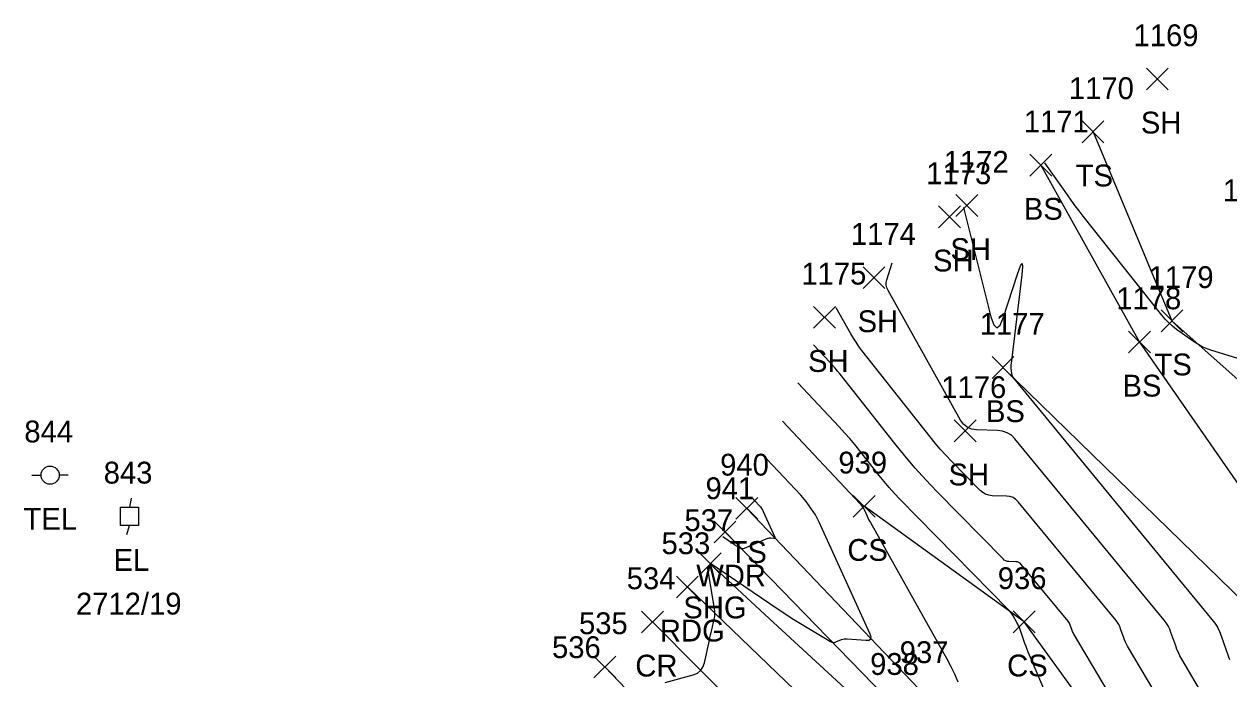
# Model space of a CAD drawing. Extents: x 1592612 to 1596497, y 111838 to 113741.
# Drawn here: x 1592611.9 to 1592722.3, y 113631.2 to 113691.2 of the extents above; entities that cross this region are included whole.
import ezdxf

# ---------------------------------------------------------------- set-up
doc = ezdxf.new("R2010")
doc.units = 0
for name, color, linetype in [('L_A', 7, 'Continuous'), ('L_I', 7, 'Continuous'), ('L_TIC', 7, 'Continuous'), ('LAWA', 7, 'Continuous'), ('LELB', 7, 'Continuous'), ('LSOGCMA', 7, 'Continuous'), ('LSOGCMI', 7, 'Continuous'), ('P_A', 7, 'Continuous'), ('P_I', 7, 'Continuous'), ('P_TIC', 7, 'Continuous'), ('PEU', 7, 'Continuous'), ('PRC', 7, 'Continuous'), ('PSU', 7, 'Continuous'), ('U_A', 7, 'Continuous'), ('U_C', 7, 'Continuous'), ('U_I', 7, 'Continuous'), ('UEPT', 7, 'Continuous'), ('UP', 7, 'Continuous')]:
    doc.layers.add(name, color=color, linetype=linetype)

msp = doc.modelspace()

# ---------------------------------------------------------------- linework, layer by layer
at = {"layer": 'L_TIC'}
for points in [[(1592714.73, 113685.21), (1592716.73, 113687.21)], [(1592716.73, 113685.21), (1592714.73, 113687.21)], [(1592708.84, 113680.36), (1592710.84, 113682.36)], [(1592710.84, 113680.36), (1592708.84, 113682.36)], [(1592704.06, 113677.31), (1592706.06, 113679.31)], [(1592706.06, 113677.31), (1592704.06, 113679.31)], [(1592697.28, 113673.62), (1592699.28, 113675.62)], [(1592699.28, 113673.62), (1592697.28, 113675.62)], [(1592695.69, 113672.57), (1592697.69, 113674.57)], [(1592697.69, 113672.57), (1592695.69, 113674.57)], [(1592688.78, 113667.01), (1592690.78, 113669.01)], [(1592690.78, 113667.01), (1592688.78, 113669.01)], [(1592684.24, 113663.37), (1592686.24, 113665.37)], [(1592686.24, 113663.37), (1592684.24, 113665.37)], [(1592716.07, 113663.05), (1592718.07, 113665.05)], [(1592718.07, 113663.05), (1592716.07, 113665.05)], [(1592713.1, 113661.11), (1592715.1, 113663.11)], [(1592715.1, 113661.11), (1592713.1, 113663.11)], [(1592700.59, 113658.77), (1592702.59, 113660.77)], [(1592702.59, 113658.77), (1592700.59, 113660.77)], [(1592697.12, 113652.97), (1592699.12, 113654.97)], [(1592699.12, 113652.97), (1592697.12, 113654.97)], [(1592677.13, 113645.87), (1592679.13, 113647.87)], [(1592679.13, 113645.87), (1592677.13, 113647.87)], [(1592687.88, 113646.06), (1592689.88, 113648.06)], [(1592689.88, 113646.06), (1592687.88, 113648.06)], [(1592675.13, 113643.71), (1592677.13, 113645.71)], [(1592677.13, 113643.71), (1592675.13, 113645.71)], [(1592702.53, 113635.47), (1592704.53, 113637.47)], [(1592704.53, 113635.47), (1592702.53, 113637.47)]]:
    msp.add_lwpolyline(points, dxfattribs=at)
at = {"layer": 'LAWA'}
msp.add_lwpolyline([(1592820.85, 113504.77), (1592798.01, 113529.8), (1592767.97, 113554.76), (1592744.7, 113575.87), (1592731.75, 113590.19), (1592719.52, 113602.85), (1592702.93, 113618.44), (1592691.78, 113628.61), (1592676.13, 113644.71)], dxfattribs=at)
at = {"layer": 'LELB'}
for points in [[(1592709.84, 113681.36), (1592717.07, 113664.05), (1592736.4, 113646.87), (1592747.92, 113636.87), (1592767.3, 113626.29), (1592768.75, 113634.43)], [(1592705.06, 113678.31), (1592714.1, 113662.11), (1592730.21, 113638.89), (1592746.13, 113634.3), (1592770.55, 113620.75), (1592772.37, 113634.85)], [(1592701.59, 113659.77), (1592726.1, 113635.89), (1592737.45, 113625.12), (1592757.27, 113620.55), (1592765.53, 113604.49), (1592785.22, 113593.36), (1592785.14, 113579.95), (1592783.1, 113567.94), (1592785.83, 113560.01), (1592797.4, 113544.62), (1592809.21, 113533.64), (1592811.43, 113524.52), (1592820.84, 113522.69), (1592826.43, 113512.91)], [(1592694.49, 113629.69), (1592678.13, 113646.87)], [(1592719.55, 113614.32), (1592703.53, 113636.47), (1592688.88, 113647.06)]]:
    msp.add_lwpolyline(points, dxfattribs=at)
at = {"layer": 'LSOGCMA'}
for points in [[(1592721.65, 113626.83), (1592717.96, 113633.06), (1592717.8, 113633.35), (1592717.66, 113633.65), (1592717.53, 113633.95), (1592717.41, 113634.26), (1592716.98, 113635.51), (1592716.86, 113635.81), (1592716.71, 113636.11), (1592716.54, 113636.38), (1592716.34, 113636.64), (1592702.69, 113653.24), (1592702.36, 113653.56), (1592701.98, 113653.8), (1592701.56, 113653.95), (1592701.1, 113654.01), (1592699.16, 113654.06), (1592698.7, 113654.13), (1592698.31, 113654.3), (1592697.98, 113654.57), (1592697.71, 113654.94), (1592691.06, 113666.83), (1592690.95, 113667.07), (1592690.9, 113667.31), (1592690.9, 113667.56), (1592690.96, 113667.81), (1592691.45, 113669.35)], [(1592674.81, 113641.86), (1592681, 113637.63), (1592681.32, 113637.41), (1592681.64, 113637.2), (1592681.97, 113637), (1592682.29, 113636.79), (1592685.8, 113634.67), (1592685.92, 113634.61), (1592686.04, 113634.59), (1592686.16, 113634.59), (1592686.28, 113634.63), (1592686.79, 113634.85), (1592686.91, 113634.89), (1592687.04, 113634.92), (1592687.17, 113634.93), (1592687.31, 113634.93), (1592689.03, 113634.78), (1592689.31, 113634.8), (1592689.46, 113634.89), (1592689.5, 113635.07), (1592689.42, 113635.33), (1592684.74, 113645.6), (1592684.4, 113646.27), (1592684, 113646.9), (1592683.56, 113647.51), (1592683.07, 113648.07), (1592679.97, 113651.38)], [(1592670.63, 113630.92), (1592673.21, 113631.63), (1592673.59, 113631.78), (1592673.88, 113632.01), (1592674.1, 113632.32), (1592674.24, 113632.71), (1592674.7, 113634.78), (1592674.75, 113635.02), (1592674.81, 113635.27), (1592674.86, 113635.51), (1592674.92, 113635.75), (1592675.14, 113636.71), (1592675.18, 113636.95), (1592675.2, 113637.2), (1592675.2, 113637.44), (1592675.17, 113637.68), (1592674.51, 113641.52)]]:
    msp.add_lwpolyline(points, dxfattribs=at)
at = {"layer": 'LSOGCMI'}
for points in [[(1592736.06, 113656.62), (1592720.72, 113661.33), (1592720.28, 113661.49), (1592719.85, 113661.68), (1592719.44, 113661.9), (1592719.04, 113662.16), (1592717.5, 113663.27), (1592717.12, 113663.56), (1592716.77, 113663.88), (1592716.44, 113664.21), (1592716.13, 113664.57), (1592708.94, 113673.65), (1592708.57, 113674.12), (1592708.2, 113674.6), (1592707.84, 113675.09), (1592707.49, 113675.58), (1592705.41, 113678.53)], [(1592697.98, 113674.42), (1592700.49, 113664.43), (1592700.75, 113663.67), (1592701.03, 113663.42), (1592701.33, 113663.65), (1592701.64, 113664.39), (1592702.92, 113668.34), (1592703.19, 113669.08), (1592703.34, 113669.31), (1592703.38, 113669.03), (1592703.31, 113668.26), (1592702.33, 113660.14), (1592702.32, 113660.02), (1592702.31, 113659.91), (1592702.31, 113659.79), (1592702.32, 113659.68), (1592702.37, 113659.22), (1592702.39, 113659.1), (1592702.43, 113659), (1592702.48, 113658.9), (1592702.54, 113658.81), (1592720.73, 113636.7), (1592721, 113636.35), (1592721.23, 113635.98), (1592721.43, 113635.59), (1592721.59, 113635.18), (1592722.22, 113633.35), (1592722.35, 113633.01)], [(1592720.71, 113621.24), (1592713.01, 113634.23), (1592712.91, 113634.42), (1592712.81, 113634.62), (1592712.73, 113634.81), (1592712.65, 113635.02), (1592712.36, 113635.84), (1592712.29, 113636.04), (1592712.19, 113636.23), (1592712.08, 113636.41), (1592711.95, 113636.59), (1592702.99, 113647.47), (1592702.76, 113647.69), (1592702.51, 113647.86), (1592702.23, 113647.96), (1592701.92, 113648), (1592700.6, 113648.03), (1592700.29, 113648.07), (1592700, 113648.16), (1592699.73, 113648.31), (1592699.49, 113648.52), (1592696.86, 113651.2), (1592696.35, 113651.73), (1592695.85, 113652.28), (1592695.38, 113652.84), (1592694.91, 113653.41), (1592688.67, 113661.34), (1592688.39, 113661.7), (1592688.13, 113662.08), (1592687.89, 113662.46), (1592687.66, 113662.85), (1592686.31, 113665.23)], [(1592719.77, 113615.64), (1592708.06, 113635.4), (1592708.01, 113635.49), (1592707.97, 113635.59), (1592707.92, 113635.68), (1592707.89, 113635.78), (1592707.75, 113636.17), (1592707.71, 113636.27), (1592707.67, 113636.36), (1592707.61, 113636.44), (1592707.55, 113636.53), (1592703.27, 113641.73), (1592703.16, 113641.84), (1592703.04, 113641.91), (1592702.91, 113641.96), (1592702.76, 113641.98), (1592702.13, 113642), (1592701.98, 113642.01), (1592701.84, 113642.06), (1592701.71, 113642.13), (1592701.6, 113642.23), (1592695.54, 113648.4), (1592694.53, 113649.47), (1592693.54, 113650.55), (1592692.59, 113651.67), (1592691.67, 113652.81), (1592686.67, 113659.15), (1592686.44, 113659.44), (1592686.21, 113659.72), (1592685.97, 113659.99), (1592685.72, 113660.26), (1592684.22, 113661.86)], [(1592709.06, 113621.56), (1592704.01, 113633.41), (1592703.9, 113633.68), (1592703.8, 113633.94), (1592703.7, 113634.21), (1592703.6, 113634.48), (1592703.15, 113635.77), (1592703.09, 113635.94), (1592703.02, 113636.1), (1592702.95, 113636.25), (1592702.87, 113636.41), (1592702.52, 113637.02), (1592702.43, 113637.17), (1592702.33, 113637.31), (1592702.22, 113637.45), (1592702.11, 113637.57), (1592692.15, 113647.72), (1592691.66, 113648.24), (1592691.17, 113648.77), (1592690.71, 113649.32), (1592690.25, 113649.88), (1592688.47, 113652.15), (1592688.02, 113652.71), (1592687.55, 113653.26), (1592687.08, 113653.8), (1592686.59, 113654.33), (1592682.8, 113658.36)], [(1592681.38, 113654.87), (1592688.5, 113647.29), (1592688.61, 113647.17), (1592688.7, 113647.04), (1592688.79, 113646.9), (1592688.86, 113646.75), (1592689.14, 113646.15), (1592689.21, 113646), (1592689.28, 113645.85), (1592689.36, 113645.71), (1592689.44, 113645.56), (1592696.44, 113633.07), (1592696.81, 113632.39), (1592697.14, 113631.7), (1592697.44, 113630.99)], [(1592678.55, 113647.89), (1592679.25, 113647.14), (1592679.37, 113647.01), (1592679.47, 113646.87), (1592679.55, 113646.73), (1592679.63, 113646.58), (1592680.7, 113644.24), (1592680.72, 113644.18), (1592680.71, 113644.14), (1592680.67, 113644.12), (1592680.61, 113644.12), (1592680.31, 113644.14), (1592680.23, 113644.15), (1592680.16, 113644.14), (1592680.09, 113644.12), (1592680.02, 113644.1), (1592677.88, 113643.18), (1592677.79, 113643.15), (1592677.7, 113643.15), (1592677.61, 113643.17), (1592677.52, 113643.21), (1592677.1, 113643.46), (1592677.05, 113643.49), (1592677, 113643.53), (1592676.95, 113643.56), (1592676.9, 113643.59), (1592675.92, 113644.26)]]:
    msp.add_lwpolyline(points, dxfattribs=at)
at = {"layer": 'P_TIC'}
for points in [[(1592673.78, 113640.79), (1592675.78, 113642.79)], [(1592675.78, 113640.79), (1592673.78, 113642.79)], [(1592671.68, 113638.67), (1592673.68, 113640.67)], [(1592673.68, 113638.67), (1592671.68, 113640.67)], [(1592668.48, 113635.46), (1592670.48, 113637.46)], [(1592670.48, 113635.46), (1592668.48, 113637.46)], [(1592664.11, 113631.34), (1592666.11, 113633.34)], [(1592666.11, 113631.34), (1592664.11, 113633.34)]]:
    msp.add_lwpolyline(points, dxfattribs=at)
at = {"layer": 'PEU'}
for points in [[(1592852.27, 113463.85), (1592836.28, 113474.06), (1592819.97, 113487.62), (1592800.66, 113505.5), (1592780.78, 113527.09), (1592759.62, 113549.57), (1592738.37, 113572.94), (1592716.19, 113596.28), (1592693.96, 113619.19), (1592672.68, 113639.67)], [(1592744.66, 113547.12), (1592739.3, 113552.77), (1592733.95, 113558.42), (1592728.59, 113564.06), (1592723.23, 113570.05), (1592717.86, 113576.03), (1592712.5, 113582.01), (1592707.13, 113587.99), (1592701.82, 113593.63), (1592696.51, 113599.28), (1592691.19, 113604.92), (1592685.88, 113610.56), (1592680.69, 113616.01), (1592675.49, 113621.45), (1592670.3, 113626.9), (1592665.11, 113632.34)]]:
    msp.add_lwpolyline(points, dxfattribs=at)
at = {"layer": 'PRC'}
msp.add_lwpolyline([(1592851.01, 113460.15), (1592833.1, 113469.52), (1592815.86, 113483.2), (1592796.57, 113501.27), (1592777.29, 113523.93), (1592756.26, 113546.33), (1592734.61, 113569.35), (1592712.84, 113593.06), (1592690.49, 113615.3), (1592669.48, 113636.46)], dxfattribs=at)
at = {"layer": 'PSU'}
msp.add_lwpolyline([(1592674.78, 113641.79), (1592680.18, 113636.79), (1592685.59, 113631.79), (1592691, 113626.79), (1592696.41, 113621.79), (1592702.22, 113616.19), (1592708.04, 113610.6), (1592713.85, 113605.01), (1592719.67, 113599.42), (1592725.13, 113593.48), (1592730.59, 113587.54), (1592736.05, 113581.6), (1592741.51, 113575.66), (1592747.34, 113570.26), (1592753.17, 113564.87), (1592759, 113559.47), (1592764.83, 113554.08), (1592770.05, 113548.46), (1592775.26, 113542.84)], dxfattribs=at)
at = {"layer": 'UEPT'}
for p, q in [((1592621.74, 113647.8), (1592621.58, 113646.97)), ((1592620.74, 113645.3), (1592620.74, 113646.97)), ((1592620.74, 113646.97), (1592622.41, 113646.97)), ((1592622.41, 113646.97), (1592622.41, 113645.3)), ((1592621.58, 113646.14), (1592621.58, 113646.14)), ((1592622.41, 113645.3), (1592620.74, 113645.3)), ((1592621.33, 113644.47), (1592621.58, 113645.3))]:
    msp.add_line(p, q, dxfattribs=at)
at = {"layer": 'UP'}
for p, q in [((1592612.64, 113649.91), (1592613.46, 113649.91)), ((1592614.3, 113649.91), (1592614.3, 113649.91)), ((1592615.96, 113649.91), (1592615.13, 113649.91)), ((1592615.13, 113649.91), (1592615.13, 113649.91)), ((1592615.96, 113649.91), (1592615.96, 113649.91))]:
    msp.add_line(p, q, dxfattribs=at)
msp.add_circle((1592614.3, 113649.91), 0.833, dxfattribs=at)

# ---------------------------------------------------------------- texts
at = {"layer": 'L_A'}
for s, p in [('SH', (1592714.22, 113681.21)), ('TS', (1592708.25, 113676.36)), ('BS', (1592703.5, 113673.31)), ('SH', (1592696.77, 113669.62)), ('SH', (1592695.18, 113668.57)), ('SH', (1592688.27, 113663.01)), ('SH', (1592683.73, 113659.37)), ('TS', (1592715.47, 113659.05)), ('BS', (1592712.54, 113657.11)), ('BS', (1592700.03, 113654.77)), ('SH', (1592696.6, 113648.97)), ('TS', (1592676.54, 113641.87)), ('CS', (1592687.33, 113642.06)), ('WDR', (1592673.49, 113639.71)), ('CS', (1592701.97, 113631.47))]:
    msp.add_text(s, height=2, dxfattribs=at).set_placement(p)
at = {"layer": 'L_I'}
for s, p in [('1169', (1592713.55, 113689.21)), ('1170', (1592707.63, 113684.36)), ('1171', (1592703.5, 113681.31)), ('1172', (1592696.16, 113677.62)), ('1173', (1592694.56, 113676.57)), ('1168', (1592721.73, 113675)), ('1174', (1592687.66, 113671.01)), ('1175', (1592683.12, 113667.37)), ('1179', (1592714.93, 113667.05)), ('1178', (1592711.97, 113665.11)), ('1177', (1592699.46, 113662.77)), ('1176', (1592695.94, 113656.97)), ('939', (1592686.51, 113650.06)), ('940', (1592675.68, 113649.87)), ('941', (1592674.34, 113647.71)), ('936', (1592701.11, 113639.47)), ('937', (1592692.13, 113632.69)), ('938', (1592689.42, 113631.61))]:
    msp.add_text(s, height=2, dxfattribs=at).set_placement(p)
at = {"layer": 'P_A'}
for s, p in [('SHG', (1592672.31, 113636.79)), ('RDG', (1592670.16, 113634.67)), ('CR', (1592667.91, 113631.46))]:
    msp.add_text(s, height=2, dxfattribs=at).set_placement(p)
at = {"layer": 'P_I'}
for s, p in [('537', (1592672.41, 113644.79)), ('533', (1592670.31, 113642.67)), ('534', (1592667.12, 113639.46)), ('535', (1592662.75, 113635.34)), ('536', (1592660.28, 113633.15))]:
    msp.add_text(s, height=2, dxfattribs=at).set_placement(p)
at = {"layer": 'U_A'}
for s, p in [('TEL', (1592611.86, 113644.91)), ('EL', (1592620.11, 113641.14))]:
    msp.add_text(s, height=2, dxfattribs=at).set_placement(p)
at = {"layer": 'U_C'}
msp.add_text('2712/19', height=2, dxfattribs=at).set_placement((1592616.67, 113637.14))
at = {"layer": 'U_I'}
for s, p in [('844', (1592611.94, 113652.91)), ('843', (1592619.21, 113649.14))]:
    msp.add_text(s, height=2, dxfattribs=at).set_placement(p)

doc.saveas('drawing.dxf')
